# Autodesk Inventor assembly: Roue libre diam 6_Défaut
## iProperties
Shininess: 64.0
Length Units: 11269
Angle Units: 11279
Time Units: 11290
Mass Units: 11283
Length Display Precision: 3
Angle Display Precision: 2
Compacted: True
Created: 2006-01
Part Number: Roue libre diam 6_Défaut
Document SubType Name: Assembly
Designer: riri
Density: 0.0
Volumn: 0.0
Area: 0.0
PropertySet Name: Model Information
Control State: 0
Master: False
Checked Out: False
Author: riri
